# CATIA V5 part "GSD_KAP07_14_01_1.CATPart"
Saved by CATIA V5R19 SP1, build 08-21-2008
Part number: GSD_KAP07_14_01
Definition: Beispielmodell für die Funktion Eckenverrundung / EdgeFillet
Description: CATIA V5 Flächenmodellierung  Copyright (c) 2009 Maik Hertha IT Consultants
Bounding box of the stored display mesh (mm): x -56.552 to 55.86, y -40.308 to 65.732, z -10 to 30
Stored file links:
  \GSD_BUCH_UEBUNG\GSD_KAP07_14_01_1.CATPart
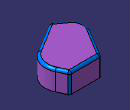
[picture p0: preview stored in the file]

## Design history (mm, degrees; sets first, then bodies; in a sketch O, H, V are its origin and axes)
AxisSystem1 "Absolute Axis System": origin (0, 0, 0), X (1, 0, 0), Y (0, 1, 0), Z (0, 0, 1)
Set1 "Edge Support"
  Plane1: type Equation, A 0, B 0, C 1, Length -10
  Point1: type OnPlane, Support Plane1, Direction (1, 0, 0), H 10, V 10
  Sketch1 on Plane1, origin (10, 10, -10), H (0, 1, 0), V (-1, 0, 0)
    line L1 (-51.3593, 33.255) -> (-33.8184, 56.4068)
    arc A1 centre (-13.4029, 40.9391) radius 25.6134 from (-33.8184, 56.4068) to (-0.1418, 62.8523) cw
    line L2 (-0.1418, 62.8523) -> (55.7324, 29.0392)
    line L3 (55.7324, 29.0392) -> (55.7324, -32.7926)
    line L4 (55.7324, -32.7926) -> (35.6076, -42.197)
    arc A2 centre (19.1105, -6.8942) radius 38.9672 from (35.6076, -42.197) to (-14.0743, -27.3201) cw
    line L5 (-14.0743, -27.3201) -> (-51.3593, 33.255)
    curve C1
    construction line L6 (-1.4464, -47.8359) -> (-25.97, -7.9936)
    angle L5 L6 = 0
    tangency: A1 L1, L2 A1, A2 L4, L6 A2, A2 L5
    vertical: L3 V
  Split1: ToCut Plane1, Cutting Sketch1.C1
  Extrude1: Lim1 40, Lim2 0, Element1 Split1, Direction Plane1
Set2 "Edge 1"
  DatumSurface1: linked copy from another document
  Fillet1: radius 5, on face of DatumSurface1; edge [face of DatumSurface1 | face of DatumSurface1] (x3)
Body1 (main body)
